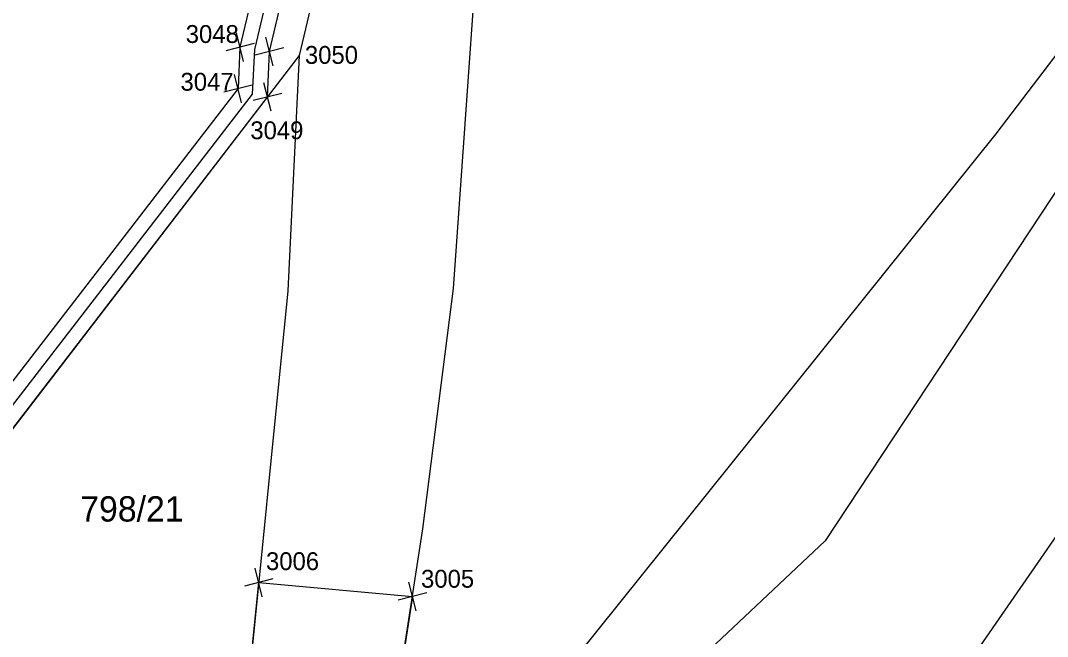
# Model space of a CAD drawing. Extents: x -7476540 to -746055, y -11317203 to -1129777.
# Drawn here: x -747615.6 to -747546.5, y -1131689.8 to -1131648.4 of the extents above; entities that cross this region are included whole.
import ezdxf

# ---------------------------------------------------------------- set-up
doc = ezdxf.new("R2010")
doc.units = 0
for name, color, linetype in [('_TRASA_vedení kabelu_CEZ', 7, 'Continuous'), ('Hranice parcel', 7, 'Continuous'), ('obvod_stavby_DZ_DO_ostatní', 7, 'Continuous'), ('obvod_stavby_DZ_DO_ZPF', 7, 'Continuous'), ('Parcelní čísla', 7, 'Continuous'), ('Vrstva 60', 7, 'Continuous')]:
    doc.layers.add(name, color=color, linetype=linetype)

# ---------------------------------------------------------------- blocks, each defined once
blk = doc.blocks.new('POINT_DISPLAY')
for p, q in [((-0.7, -0.7), (0.7, 0.7)), ((-0.7, 0.7), (0.7, -0.7))]:
    blk.add_line(p, q)

msp = doc.modelspace()

# ---------------------------------------------------------------- linework, layer by layer
at = {"layer": '_TRASA_vedení kabelu_CEZ'}
msp.add_lwpolyline([(-747606.661, -1131708.945), (-747603.525, -1131695.366), (-747628.041, -1131689.704), (-747599.968, -1131653.349), (-747599.823, -1131650.348), (-747590.152, -1131609.621), (-747577.851, -1131574.826), (-747576.114, -1131566.001), (-747573.02, -1131550.257), (-747574.144, -1131533.397), (-747574.335, -1131530.458), (-747575.576, -1131507.342), (-747576.376, -1131492.518), (-747578.396, -1131453.504), (-747579.216, -1131437.56), (-747579.881, -1131425.586), (-747579.541, -1131395.963)], dxfattribs=at)
at = {"layer": 'Hranice parcel'}
msp.add_line((-747596.84, -1131650.77), (-747626.3, -1131689.08), dxfattribs=at)
for points in [[(-747443.45, -1131514.26), (-747480.55, -1131563.87), (-747518.42, -1131614.59), (-747550, -1131656.02), (-747584.22, -1131698.64)], [(-747573.17, -1131566.58), (-747574.95, -1131575.62), (-747587.27, -1131610.47), (-747596.84, -1131650.77)], [(-747512.18, -1131613.29), (-747532.53, -1131639.52), (-747561.47, -1131683.37), (-747579.28, -1131700.12)], [(-747512.18, -1131613.29), (-747502.43, -1131618.94), (-747504.69, -1131623.44), (-747559.41, -1131702.48)], [(-747590.72, -1131696.79), (-747588.52, -1131682.57), (-747586.46, -1131666.42), (-747584.9, -1131644.26), (-747582.84, -1131630.56)], [(-747596.84, -1131650.77), (-747597.6, -1131666.57), (-747600.45, -1131695.05)]]:
    msp.add_lwpolyline(points, dxfattribs=at)
at = {"layer": 'obvod_stavby_DZ_DO_ostatní'}
msp.add_lwpolyline([(-747600.45, -1131695.05), (-747599.561, -1131686.168), (-747589.221, -1131687.1), (-747590.72, -1131696.79)], dxfattribs=at)
at = {"layer": 'obvod_stavby_DZ_DO_ZPF'}
for points in [[(-747626.3, -1131689.08), (-747598.976, -1131653.548), (-747598.829, -1131650.489), (-747589.191, -1131609.904), (-747576.884, -1131575.091), (-747575.885, -1131570.018), (-747572.013, -1131550.322), (-747572.999, -1131535.536), (-747574.449, -1131509.682), (-747577.276, -1131455.803), (-747578.745, -1131428.004), (-747578.878, -1131425.603), (-747578.57, -1131398.486)], [(-747580.6, -1131401.092), (-747580.875, -1131425.728), (-747580.61, -1131430.488), (-747579.148, -1131458.314), (-747576.317, -1131512.183), (-747574.847, -1131537.872), (-747574.026, -1131550.193), (-747578.601, -1131573.455), (-747578.818, -1131574.561), (-747591.112, -1131609.338), (-747600.818, -1131650.207), (-747600.951, -1131652.987), (-747628.404, -1131688.537)]]:
    msp.add_lwpolyline(points, dxfattribs=at)
at = {"layer": 'Vrstva 60'}
for p, q in [((-747600.818, -1131650.207), (-747600.818, -1131650.207)), ((-747598.829, -1131650.489), (-747598.829, -1131650.489)), ((-747600.951, -1131652.987), (-747600.951, -1131652.987)), ((-747598.943, -1131653.591), (-747598.943, -1131653.591)), ((-747599.561, -1131686.168), (-747599.561, -1131686.168)), ((-747589.221, -1131687.1), (-747589.221, -1131687.1))]:
    msp.add_line(p, q, dxfattribs=at)

# ---------------------------------------------------------------- block references
at = {"layer": 'obvod_stavby_DZ_DO_ostatní', "rotation": 149.23018890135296}
for p in [(-747599.561, -1131686.168), (-747589.221, -1131687.1)]:
    msp.add_blockref('POINT_DISPLAY', p, dxfattribs=at)
at = {"layer": 'obvod_stavby_DZ_DO_ZPF', "rotation": 149.23018890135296}
for p in [(-747600.817, -1131650.206), (-747598.828, -1131650.488), (-747600.951, -1131652.986), (-747598.975, -1131653.547)]:
    msp.add_blockref('POINT_DISPLAY', p, dxfattribs=at)

# ---------------------------------------------------------------- texts
at = {"layer": 'Parcelní čísla'}
msp.add_text('798/21', height=1.7, dxfattribs=at).set_placement((-747611.56, -1131682.07))
at = {"layer": 'Vrstva 60'}
for s, p in [('3048', (-747604.467, -1131649.916)), ('3050', (-747596.453, -1131651.32)), ('3047', (-747604.817, -1131653.124)), ('3049', (-747600.124, -1131656.385)), ('3006', (-747599.07, -1131685.333)), ('3005', (-747588.646, -1131686.514))]:
    msp.add_text(s, height=1.2, dxfattribs=at).set_placement(p)

doc.saveas('drawing.dxf')
